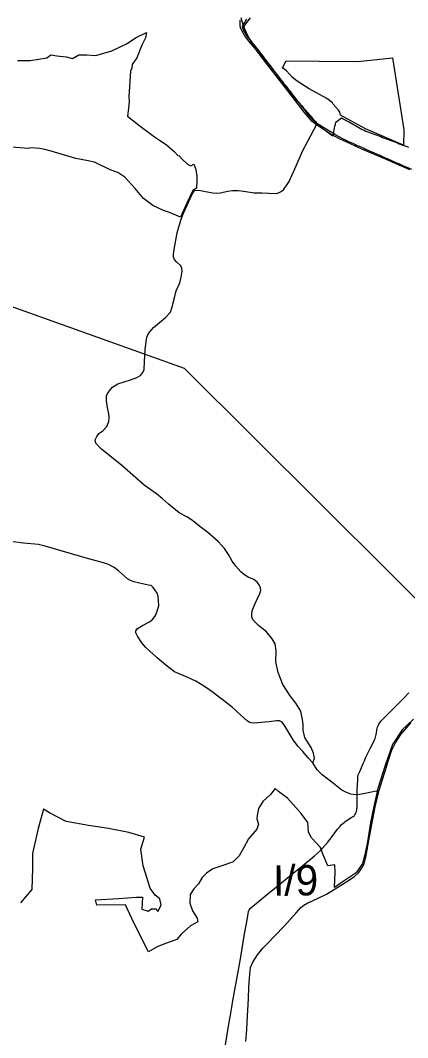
# Model space of a CAD drawing. Extents: x -789162 to -606354, y -1062736 to -945481.
# Drawn here: x -727772 to -725860, y -990079 to -985051 of the extents above; entities that cross this region are included whole.
import ezdxf

# ---------------------------------------------------------------- set-up
doc = ezdxf.new("R2010")
doc.units = 0
for name, color, linetype in [('_SIRSI VZTAHY CHKO HRANICE', 7, 'Continuous'), ('_SIRSI VZTAHY_ELEKTRICKE VEDENI VN 110 kV N', 7, 'Continuous'), ('_SIRSI VZTAHY_NATURA_EVL', 7, 'Continuous'), ('_SIRSI VZTAHY_OP vodnich zdroju II stupne', 7, 'Continuous'), ('_SIRSI VZTAHY_SILNICE I TRIDY_NAVRH', 7, 'Continuous'), ('_SIRSI VZTAHY_SILNICE I TRIDY_STAV', 7, 'Continuous'), ('_SIRSI VZTAHY_SILNICE III TRIDY_STAV', 7, 'Continuous'), ('_SIRSI VZTAHY_SILNICE_STAV_POPIS', 7, 'Continuous'), ('_SIRSI VZTAHY_VTL PLYNOVOD', 7, 'Continuous')]:
    doc.layers.add(name, color=color, linetype=linetype)

msp = doc.modelspace()

# ---------------------------------------------------------------- linework, layer by layer
at = {"layer": '_SIRSI VZTAHY CHKO HRANICE'}
msp.add_lwpolyline([(-726638.4, -985037.6), (-726676.1, -985086.8), (-726675.4, -985089.3), (-726672.8, -985096.4), (-726671, -985100.6), (-726669.4, -985103.2), (-726663.9, -985111.3), (-726661.5, -985115.3), (-726651.8, -985129.8), (-726647.8, -985135.8), (-726643.4, -985142.3), (-726639.8, -985147), (-726633, -985155.3), (-726626.7, -985163), (-726613.7, -985178.3), (-726611.8, -985180.4), (-726608.2, -985185.7), (-726605.6, -985187.4), (-726602, -985192.5), (-726592.1, -985206), (-726575.1, -985229.3), (-726568.3, -985238.2), (-726557.4, -985253.3), (-726555, -985256.1), (-726537.2, -985279), (-726527.2, -985291.5), (-726506.7, -985317.4), (-726504.6, -985320.6), (-726497, -985330.2), (-726478.2, -985354.1), (-726470.9, -985363.6), (-726466.9, -985368.6), (-726463.2, -985372.8), (-726456.6, -985381.5), (-726449.6, -985390.7), (-726444, -985397.4), (-726435.5, -985408.2), (-726424.7, -985422.4), (-726416.7, -985432.7), (-726404, -985449.2), (-726378.9, -985481.3), (-726371, -985491.2), (-726358.8, -985507), (-726342.5, -985528.2), (-726339.6, -985531.4), (-726324.2, -985548), (-726315.8, -985553.4), (-726296.4, -985565.5), (-726274.5, -985579.5), (-726264.3, -985585.9), (-726251.7, -985593.7), (-726249.3, -985595.1), (-726221.9, -985612.3), (-726221.3, -985612.6), (-726196.4, -985626.7), (-726184.6, -985633), (-726181.6, -985634.5), (-726151.7, -985648.6), (-726127.4, -985660), (-726124.7, -985660.8), (-726117.5, -985664.4), (-726112.2, -985666.9), (-726105.2, -985670.1), (-726099.3, -985672.6), (-726094.6, -985674.6), (-726080.2, -985681.3), (-726073.3, -985684.8), (-726068.6, -985686.6), (-726065.9, -985687.7), (-726045, -985696.7), (-725997.3, -985717.7), (-725977.7, -985726.3), (-725975, -985727.7), (-725961.2, -985733.9), (-725914.7, -985754.1), (-725908.5, -985757), (-725897.2, -985762.2), (-725876.8, -985771), (-725864.6, -985776.5), (-725840.5, -985786.7)], dxfattribs=at)
at = {"layer": '_SIRSI VZTAHY_ELEKTRICKE VEDENI VN 110 kV N'}
msp.add_lwpolyline([(-730001.6, -985682.4), (-726963.9, -986770.2), (-725266.3, -988459.5), (-722782.9, -988718.3), (-722012.4, -989499.6)], dxfattribs=at)
at = {"layer": '_SIRSI VZTAHY_NATURA_EVL'}
msp.add_lwpolyline([(-726655.7, -985045.1), (-726660.9, -985053.3), (-726666.2, -985061.5), (-726671.5, -985069.8), (-726676.8, -985078), (-726674.3, -985083.3), (-726676.7, -985086.8), (-726672.1, -985094), (-726667.5, -985101.2), (-726662.9, -985108.5), (-726659.8, -985115.2), (-726656.8, -985122), (-726653.7, -985128.8), (-726647.5, -985136.5), (-726641.3, -985144.2), (-726635.1, -985151.9), (-726629, -985159.6), (-726622.8, -985167.3), (-726616.6, -985175.1), (-726610.4, -985182.8), (-726604.2, -985190.5), (-726598.1, -985198.2), (-726591.9, -985205.9), (-726585.8, -985213.9), (-726579.8, -985221.8), (-726573.7, -985229.8), (-726567.7, -985237.7), (-726561.6, -985245.7), (-726555.6, -985253.6), (-726549.5, -985261.6), (-726543.5, -985269.5), (-726537.4, -985277.5), (-726531.4, -985285.4), (-726525.3, -985293.4), (-726519.3, -985301.3), (-726513.2, -985309.3), (-726507.2, -985317.2), (-726501.1, -985325.2), (-726495.1, -985333.2), (-726489, -985341.1), (-726483, -985349.1), (-726476.9, -985357), (-726470.9, -985365), (-726464.8, -985372.9), (-726458.8, -985380.9), (-726452.7, -985388.8), (-726446.7, -985396.8), (-726440.6, -985404.7), (-726434.6, -985412.7), (-726428.5, -985420.6), (-726422.5, -985428.6), (-726416.2, -985435.8), (-726409.9, -985443), (-726403.5, -985450.2), (-726397.2, -985457.4), (-726390.9, -985464.6), (-726384.6, -985471.8), (-726378.2, -985479), (-726371.9, -985486.2), (-726365.6, -985493.5), (-726359.3, -985500.7), (-726352.9, -985507.9), (-726346.6, -985515.1), (-726340.3, -985522.3), (-726334, -985529.5), (-726327.6, -985536.7), (-726321.3, -985543.9), (-726315.5, -985551.2), (-726309.7, -985558.5), (-726303.9, -985565.8), (-726296.4, -985571.4), (-726289, -985577), (-726281.5, -985582.6), (-726274.1, -985588.2), (-726266.6, -985593.9), (-726259.1, -985599.5), (-726251.7, -985605.1), (-726244.2, -985610.8), (-726236.8, -985616.4), (-726229.3, -985622), (-726229.1, -985620.1), (-726228.1, -985620.8), (-726226.2, -985611.4), (-726224.4, -985601.9), (-726222.6, -985592.4), (-726220.7, -985583), (-726218.9, -985573.5), (-726217.1, -985564.1), (-726215.2, -985554.6), (-726208, -985549), (-726200.8, -985543.4), (-726193.6, -985537.8), (-726186.4, -985532.2), (-726177.9, -985537), (-726169.3, -985541.7), (-726160.8, -985546.5), (-726152.2, -985551.2), (-726143.7, -985556), (-726135.1, -985560.8), (-726126.6, -985565.5), (-726118.1, -985570.3), (-726109.5, -985575.1), (-726101, -985579.8), (-726092.4, -985584.6), (-726083.9, -985589.4), (-726075.3, -985594.1), (-726066.2, -985597.6), (-726057, -985601.1), (-726047.8, -985604.6), (-726038.7, -985608), (-726029.5, -985611.5), (-726020.4, -985615), (-726011.2, -985618.5), (-726002.1, -985622), (-725992.9, -985625.4), (-725983.8, -985628.9), (-725974.6, -985632.4), (-725965.4, -985635.9), (-725956.3, -985639.3), (-725947.1, -985642.8), (-725938, -985646.3), (-725928.8, -985649.8), (-725919.7, -985653.3), (-725910.5, -985656.7), (-725901.4, -985660.2), (-725892.2, -985663.7), (-725883.1, -985667.2), (-725873.9, -985670.7), (-725864.7, -985674.1), (-725855.6, -985677.6)], dxfattribs=at)
at = {"layer": '_SIRSI VZTAHY_OP vodnich zdroju II stupne'}
for points in [[(-727786.9, -985248.8), (-727723.1, -985249.7), (-727641.3, -985236.2), (-727621.4, -985220.3), (-727591.7, -985226.5), (-727545.6, -985231.5), (-727515.2, -985239), (-727484, -985221.4), (-727444.1, -985221.4), (-727399.8, -985224.5), (-727319.9, -985201.7), (-727247.9, -985166.2), (-727200.1, -985135.8), (-727150.1, -985111.3), (-727154.2, -985137), (-727172.7, -985173.4), (-727196.7, -985235.7), (-727220.8, -985268), (-727222.4, -985287), (-727228.4, -985301.1), (-727236.9, -985426.9), (-727235, -985453.8), (-727238.6, -985484.2), (-727243.6, -985524.1), (-727197.2, -985560.3), (-727167, -985582.9), (-727131.8, -985610), (-727115.4, -985622.8), (-727085.4, -985642.1), (-727051.9, -985664), (-727013.4, -985698), (-726993.9, -985718), (-726987.9, -985720.8), (-726971, -985737.7), (-726946.6, -985761.7), (-726931.3, -985768.9), (-726915.6, -985761), (-726905.6, -985787.4), (-726900.7, -985820.9), (-726900.2, -985845.9), (-726902.8, -985880.4), (-726920.8, -985892.3), (-726950.2, -985953.9), (-726982.1, -986022.7), (-727036.5, -985999.6), (-727064.7, -985989.9), (-727117.8, -985965.8), (-727164.7, -985930.8), (-727204.8, -985882.3), (-727257, -985825.4), (-727290.5, -985801.9), (-727328, -985788.8), (-727406.2, -985752.2), (-727438.1, -985745.6), (-727498.5, -985733.7), (-727620.1, -985697.4), (-727652, -985688.4), (-727676.4, -985684.3), (-727720.5, -985679.9), (-727731.2, -985684), (-727816.2, -985676.8)], [(-725831.5, -988504.2), (-725887, -988557.1), (-725934.7, -988629.9), (-725970.4, -988733), (-726007.4, -988848.1), (-726027.3, -988936.8), (-726043.1, -989014.8), (-726059, -989111.4), (-726072.2, -989174.9), (-726082.8, -989218.6), (-726114.6, -989264.9), (-726192.6, -989316.5), (-726221.7, -989337.6), (-726217.8, -989260.9), (-726220.4, -989225.2), (-726253.5, -989229.1), (-726277.3, -989174.9), (-726290.5, -989139.2), (-726334.2, -989091.6), (-726350.1, -989063.8), (-726351.4, -989038.6), (-726352.7, -989014.8), (-726385.8, -988971.2), (-726425.5, -988926.2), (-726453.2, -988895.8), (-726498.2, -988862.7), (-726514.1, -988848.1), (-726537.9, -988877.2), (-726574.9, -988911.6), (-726596.1, -988946), (-726602.7, -988980.4), (-726604.1, -988997.6), (-726596.1, -989024.1), (-726604.1, -989047.9), (-726645.1, -989096.9), (-726670.2, -989141.8), (-726691.4, -989180.2), (-726721.8, -989209.3), (-726757.5, -989223.9), (-726822.3, -989243.7), (-726852.8, -989266.2), (-726873.9, -989287.4), (-726892.4, -989319.1), (-726914.9, -989342.9), (-726933.5, -989372), (-726934.8, -989414.4), (-726922.9, -989452.7), (-726899.1, -989488.4), (-726896.4, -989507), (-726932.1, -989526.8), (-726978.4, -989567.8), (-726999.6, -989594.3), (-727068.4, -989618.1), (-727097.5, -989630), (-727139.8, -989655.1), (-727212.6, -989510.9), (-727252.3, -989422.3), (-727395.2, -989424.9), (-727401.8, -989397.2), (-727288, -989390.5), (-727198, -989383.9), (-727168.9, -989383.9), (-727172.9, -989443.5), (-727141.2, -989454), (-727125.3, -989442.1), (-727102.8, -989442.1), (-727093.5, -989455.4), (-727076.3, -989424.9), (-727082.9, -989393.2), (-727106.8, -989374.7), (-727131.9, -989340.3), (-727166.3, -989229.1), (-727176.9, -989147.1), (-727159.7, -989087.6), (-727236.4, -989065.1), (-727337, -989045.3), (-727436.2, -989030.7), (-727546, -989010.9), (-727628, -988967.2), (-727658.4, -988950), (-727684.9, -989045.3), (-727712.7, -989168.3), (-727712.7, -989241), (-727714, -989295.3), (-727715.3, -989346.9), (-727772.2, -989413)]]:
    msp.add_lwpolyline(points, dxfattribs=at)
msp.add_lwpolyline([(-726191.5, -985518.4), (-726195.5, -985504.6), (-726200.7, -985494.3), (-726227.7, -985464.6), (-726230.9, -985459), (-726259.4, -985437.5), (-726346, -985389.1), (-726405.3, -985350.5), (-726428.1, -985333.4), (-726458.6, -985300), (-726478.2, -985285.7), (-726459.3, -985251), (-726296.4, -985252.2), (-726106.8, -985253.4), (-725934.6, -985235.9), (-725879.7, -985591.2), (-725880.6, -985667.4), (-726068.9, -985586.4)], close=True, dxfattribs=at)
at = {"layer": '_SIRSI VZTAHY_SILNICE I TRIDY_NAVRH'}
msp.add_lwpolyline([(-726683.7, -985036), (-726678.1, -985055.1), (-726671.8, -985074), (-726664.8, -985092.6), (-726657, -985111), (-726648.5, -985129), (-726639.3, -985146.6), (-726629.4, -985163.9), (-726618.9, -985180.8), (-726607.6, -985197.2), (-726595.7, -985213.2), (-726558.5, -985261.2)], dxfattribs=at)
at = {"layer": '_SIRSI VZTAHY_SILNICE I TRIDY_STAV'}
for points in [[(-726310.9, -985567.1), (-726332, -985550.1), (-726370.6, -985504.3), (-726419.3, -985441.5), (-726467.6, -985377.8), (-726508.9, -985324.6), (-726550.4, -985272.1), (-726613.5, -985189), (-726644.8, -985153.4), (-726664.7, -985126.4), (-726677.2, -985104.4), (-726682.9, -985090.8), (-726686.4, -985078.5), (-726687.5, -985050.4)], [(-726310.9, -985567.1), (-726332, -985550.1), (-726370.6, -985504.3), (-726419.3, -985441.5), (-726467.6, -985377.8), (-726508.9, -985324.6), (-726550.4, -985272.1), (-726613.5, -985189), (-726644.8, -985153.4), (-726664.7, -985126.4), (-726677.2, -985104.4), (-726682.9, -985090.8), (-726686.4, -985078.5), (-726687.5, -985050.4)], [(-725849, -985790.2), (-725973.2, -985735.6), (-726085.6, -985687.4), (-726142.6, -985660.6), (-726196.5, -985636.2), (-726243, -985611), (-726294.7, -985577.1), (-726310.9, -985567.1)], [(-725849, -985790.2), (-725973.2, -985735.6), (-726085.6, -985687.4), (-726142.6, -985660.6), (-726196.5, -985636.2), (-726243, -985611), (-726294.7, -985577.1), (-726310.9, -985567.1)], [(-726000.9, -988855.5), (-725973.5, -988766.5), (-725956.9, -988712.5), (-725939.2, -988661.4), (-725919.8, -988621.4), (-725893.4, -988580.9), (-725873.8, -988557.1), (-725842.3, -988522)], [(-726000.9, -988855.5), (-725973.5, -988766.5), (-725956.9, -988712.5), (-725939.2, -988661.4), (-725919.8, -988621.4), (-725893.4, -988580.9), (-725873.8, -988557.1), (-725842.3, -988522)], [(-726658.3, -990098.8), (-726654.4, -990038), (-726650, -989971.8), (-726646.3, -989887.4), (-726643.8, -989829.2), (-726640, -989764.8), (-726636.3, -989732.9), (-726624.4, -989705.4), (-726601.3, -989670.4), (-726574.4, -989636.7), (-726550.3, -989611.5), (-726518.1, -989576.7), (-726468.6, -989525.7), (-726410, -989461.6), (-726386.8, -989435.4), (-726372.1, -989423.9), (-726353.2, -989413.3), (-726333, -989403.7), (-726261.2, -989369.1), (-726204.3, -989334.7), (-726160.5, -989306.6), (-726122.4, -989281.6), (-726101.7, -989262.8), (-726087.4, -989243.4), (-726075.5, -989219), (-726066.4, -989186.9), (-726049.2, -989085.9), (-726020.4, -988938.2), (-726009.3, -988889.6), (-726000.9, -988855.5)], [(-726444.7, -989499.6), (-726410, -989461.6), (-726386.8, -989435.4), (-726372.1, -989423.9), (-726353.2, -989413.3), (-726333, -989403.7), (-726261.2, -989369.1), (-726204.3, -989334.7), (-726160.5, -989306.6), (-726122.4, -989281.6), (-726101.7, -989262.8), (-726087.4, -989243.4), (-726075.5, -989219), (-726066.4, -989186.9), (-726049.2, -989085.9), (-726020.4, -988938.2), (-726009.3, -988889.6), (-726000.9, -988855.5)]]:
    msp.add_lwpolyline(points, dxfattribs=at)
at = {"layer": '_SIRSI VZTAHY_SILNICE III TRIDY_STAV'}
for points in [[(-726327.8, -988721.3), (-726319.5, -988697.4), (-726324.5, -988673.6), (-726336, -988644), (-726351.3, -988620.9), (-726367.7, -988595.6), (-726376.4, -988559.6), (-726376.1, -988530.5), (-726378.8, -988506.4), (-726386.9, -988465.8), (-726412.9, -988425.4), (-726440.5, -988389.1), (-726476.2, -988334), (-726499.1, -988273.7), (-726510.9, -988221.2), (-726508.9, -988166.4), (-726514.7, -988132.9), (-726528.7, -988107.4), (-726556.7, -988073.1), (-726596.2, -988042.4), (-726621.9, -988017.6), (-726629.2, -988001.7), (-726629.4, -987981.4), (-726626.1, -987964.4), (-726613.2, -987932.4), (-726589.8, -987883.4), (-726584.8, -987868), (-726586.5, -987855.7), (-726593.5, -987841.2), (-726603.8, -987826.9), (-726620.1, -987815.1), (-726647.5, -987802.5), (-726663.8, -987792.8), (-726683.9, -987777), (-726708, -987748.7), (-726727, -987723.2), (-726744, -987691.4), (-726765.1, -987661.3), (-726793.8, -987628.5), (-726847.3, -987581.6), (-726886.1, -987552.2), (-726922.5, -987522.8), (-726950.2, -987504), (-726987.9, -987485.3), (-727042.6, -987440.8), (-727071.4, -987414.4), (-727100.3, -987391.7), (-727161, -987347.6), (-727271.1, -987250.6), (-727370.9, -987170.3), (-727384.9, -987156.9), (-727399.3, -987139.8), (-727403.1, -987124.8), (-727395.4, -987107.7), (-727384.1, -987092.4), (-727365.1, -987079.2), (-727345.2, -987058.3), (-727335.6, -987032.6), (-727334.5, -987014.4), (-727335.6, -986996.1), (-727342.6, -986964.5), (-727347, -986932), (-727346.1, -986904.2), (-727340.5, -986893.3), (-727329.6, -986877.1), (-727317.3, -986863.9), (-727304, -986854.8), (-727290.4, -986846.8), (-727228.1, -986827.5), (-727197.2, -986815.3), (-727179.7, -986805.4), (-727167.5, -986791.4), (-727161.5, -986776.6), (-727158.8, -986737.6), (-727155.3, -986679.4), (-727151.5, -986637.9), (-727147.1, -986616.2), (-727140.3, -986597.6), (-727115.5, -986569.3), (-727056, -986520), (-727030.7, -986492.2), (-727021.9, -986466.6), (-727010.7, -986422.6), (-727002.9, -986387.1), (-726985.2, -986348.5), (-726978.2, -986320.1), (-726974, -986291), (-726975.1, -986274.8), (-726979.9, -986263.8), (-727001.4, -986244), (-727011, -986233.3), (-727016.6, -986221.8), (-727015.7, -986206.2), (-727012.8, -986183.4), (-726997.2, -986100.3), (-726979.9, -986038.2), (-726967, -986003), (-726930.9, -985925.3), (-726918.8, -985900.7), (-726910.4, -985892), (-726899.5, -985889.2), (-726882.7, -985891.1), (-726823.6, -985902.9), (-726802.1, -985904.3), (-726783.6, -985902.3), (-726749.8, -985894.1), (-726724.8, -985891.1), (-726697.1, -985891.7), (-726668.1, -985894.2), (-726617.7, -985902.8), (-726578, -985903.4), (-726547.3, -985905.4), (-726506.2, -985906.1), (-726488.2, -985898.6), (-726473.7, -985888.9), (-726445.8, -985847.9), (-726410.6, -985769), (-726379.6, -985697.6), (-726351.8, -985644.1), (-726310.9, -985567.1)], [(-726327.8, -988721.3), (-726351.2, -988695.9), (-726377.8, -988664.4), (-726401.9, -988638.7), (-726425.4, -988607.6), (-726465.1, -988540.6), (-726479.2, -988520.2), (-726493.2, -988512.9), (-726508.3, -988512.9), (-726544.2, -988517.4), (-726583.4, -988521.3), (-726617, -988524.9), (-726632.1, -988523.3), (-726642.7, -988519.3), (-726651.1, -988514.2), (-726684.7, -988483.8), (-726726.9, -988445.2), (-726825.3, -988368.8), (-726853.9, -988349.4), (-726884.9, -988329.5), (-726906.4, -988316.7), (-726946, -988299.5), (-727010.7, -988271.3), (-727054.6, -988238.5), (-727096.6, -988201.2), (-727153.5, -988150.6), (-727173, -988126.7), (-727194.6, -988094.6), (-727201.9, -988078), (-727202.2, -988067.6), (-727193.6, -988056.9), (-727168.5, -988041.6), (-727135, -988024.4), (-727117.6, -988010.8), (-727104.7, -987992.1), (-727096.7, -987970.1), (-727089.1, -987942.2), (-727089.4, -987918.2), (-727091.9, -987898.9), (-727096.6, -987881.8), (-727107.8, -987865), (-727117.1, -987854), (-727126, -987844.8), (-727139.5, -987841.7), (-727183.7, -987832.4), (-727212.3, -987825.2), (-727228.2, -987819.9), (-727242.9, -987811.2), (-727258.8, -987798.3), (-727288.2, -987771.7), (-727308.9, -987754.3), (-727336.3, -987740.6), (-727362.1, -987732.5), (-727440.2, -987711.2), (-727649.1, -987649.1), (-727682, -987641.6), (-727756.7, -987634.2), (-727858.3, -987622.2)], [(-726000.9, -988855.5), (-726014.9, -988860.7), (-726077.4, -988874.1), (-726097.6, -988876.5), (-726119.4, -988878), (-726139.9, -988874.8), (-726165.3, -988865.1), (-726184.3, -988855.1), (-726226.2, -988823.1), (-726282.8, -988780.4), (-726306.1, -988754.8), (-726327.8, -988721.3)]]:
    msp.add_lwpolyline(points, dxfattribs=at)
at = {"layer": '_SIRSI VZTAHY_VTL PLYNOVOD'}
msp.add_lwpolyline([(-726759.7, -990115), (-726753, -990073.5), (-726744.7, -990022.9), (-726735, -989968.3), (-726726.4, -989918.4), (-726724.3, -989905.5), (-726724.3, -989905.5), (-726694.3, -989735.3), (-726684.4, -989679.2), (-726665.1, -989566.2), (-726656.2, -989514.9), (-726649.8, -989477.1), (-726645.6, -989455.1), (-726645, -989453.2), (-726644.2, -989451.4), (-726643, -989449.1), (-726642.1, -989447.7), (-726639.6, -989444), (-726635.3, -989438.7), (-726626, -989430.7), (-726587.9, -989398.9), (-726549.1, -989366.9), (-726501.4, -989328.6), (-726470.6, -989303.6), (-726422.9, -989264.7), (-726388.1, -989236), (-726319.6, -989180.2), (-726290.3, -989154.6), (-726287, -989151), (-726283.4, -989146.7), (-726283.3, -989146.6), (-726283.3, -989146.6), (-726279.9, -989142.7), (-726254.6, -989112.8), (-726242.7, -989098.2), (-726232, -989084.1), (-726205.6, -989048.8), (-726196.9, -989038.4), (-726191, -989031.3), (-726191, -989031.2), (-726186, -989026), (-726180.1, -989020.4), (-726173.9, -989015.2), (-726170.6, -989012.7), (-726138.9, -988991.5), (-726128.6, -988985.4), (-726124.5, -988981.9), (-726121.9, -988979), (-726121.8, -988978.9), (-726120.7, -988977.5), (-726117.8, -988973.2), (-726116.7, -988971), (-726115.4, -988968.2), (-726113.6, -988963.9), (-726112.6, -988961.1), (-726110.9, -988952.9), (-726109.7, -988938.3), (-726109.7, -988938.3), (-726109.4, -988929.1), (-726108.9, -988914.1), (-726108.5, -988889.3), (-726108.6, -988882.5), (-726108.6, -988872.3), (-726108.6, -988872.2), (-726108.6, -988872.2), (-726108.6, -988854.6), (-726108.1, -988831.1), (-726106.8, -988802.4), (-726106.8, -988802.4), (-726106.4, -988796.7), (-726105.9, -988789.3), (-726105.5, -988786.9), (-726104.8, -988783.9), (-726104, -988780.7), (-726096.8, -988764), (-726079.6, -988723.4), (-726079.6, -988723.4), (-726073.8, -988710.2), (-726065.8, -988692.6), (-726064.5, -988690), (-726054.2, -988668.8), (-726043.2, -988646.4), (-726029.3, -988618.3), (-726024.4, -988607.7), (-726022.5, -988604), (-726020.6, -988600.1), (-726020.6, -988600.1), (-726018.5, -988594.5), (-726017, -988587.9), (-726015.8, -988579.9), (-726014.4, -988571.6), (-726012.9, -988560.3), (-726012.5, -988557.7), (-726009.9, -988547.5), (-726007.6, -988541), (-726006.2, -988537), (-726002.1, -988528.9), (-725998, -988522.5), (-725994.8, -988518), (-725994.7, -988518), (-725991.3, -988513.7), (-725984.2, -988506.1), (-725958, -988479.7), (-725932.3, -988453.9), (-725906, -988427.3), (-725881.7, -988403.5), (-725854.1, -988375.3)], dxfattribs=at)

# ---------------------------------------------------------------- texts
at = {"layer": '_SIRSI VZTAHY_SILNICE_STAV_POPIS'}
msp.add_text('I/9', height=150, rotation=0.3349, dxfattribs=at).set_placement((-726524.3, -989376.8))

doc.saveas('drawing.dxf')
